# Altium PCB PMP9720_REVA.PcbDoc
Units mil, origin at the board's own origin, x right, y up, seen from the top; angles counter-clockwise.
Board outline 4500 x 2000 mil, 4 copper layers (Top Layer, MidLayer1, MidLayer2, Bottom Layer), stack 60.2 mil thick; 90 components, 43 nets, 263 pads, 74 vias.
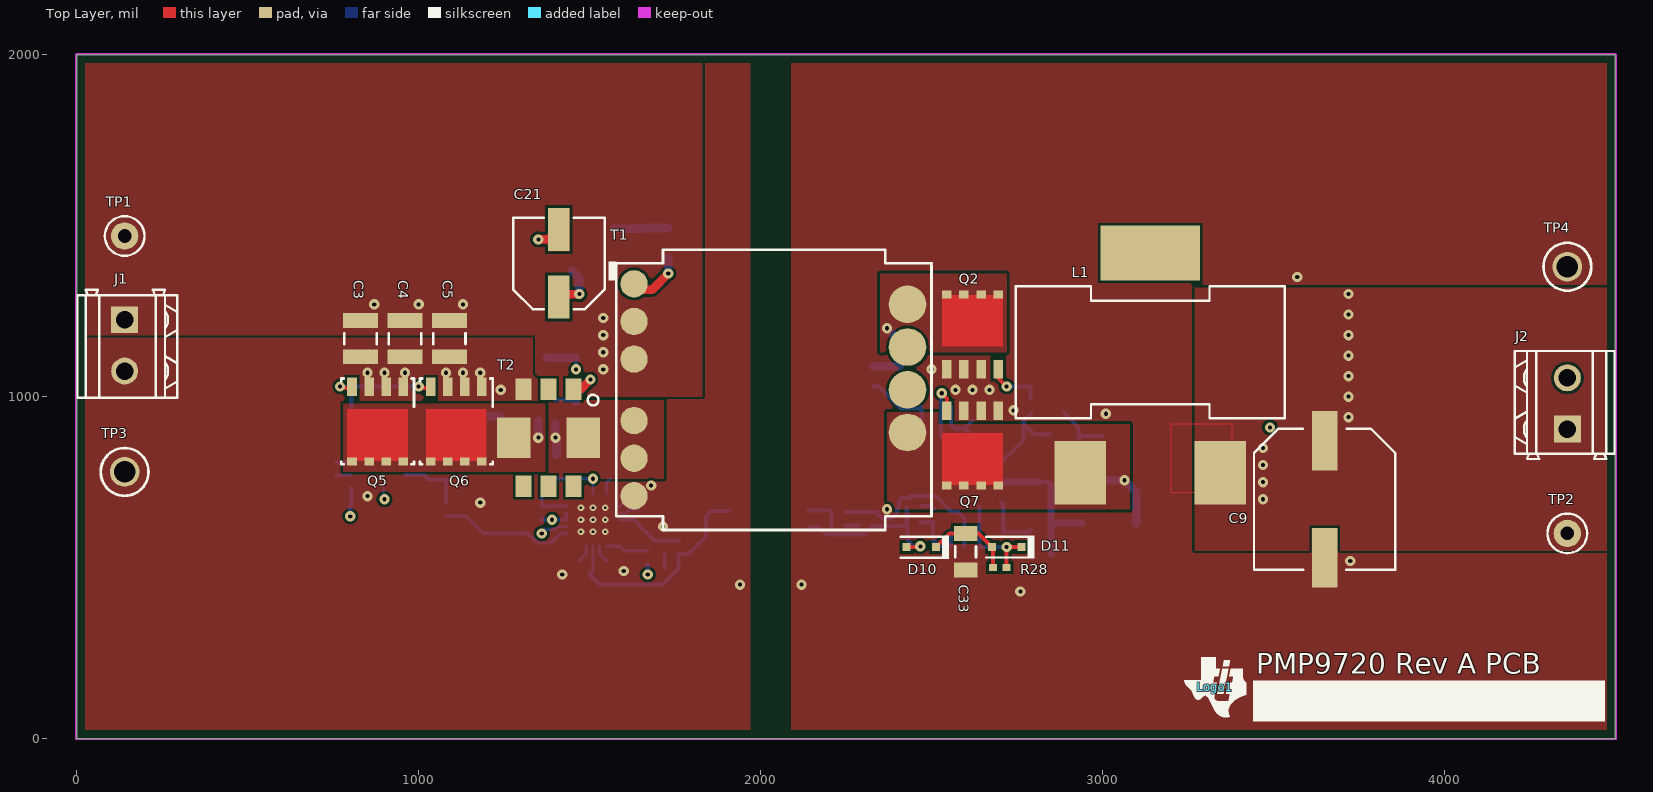
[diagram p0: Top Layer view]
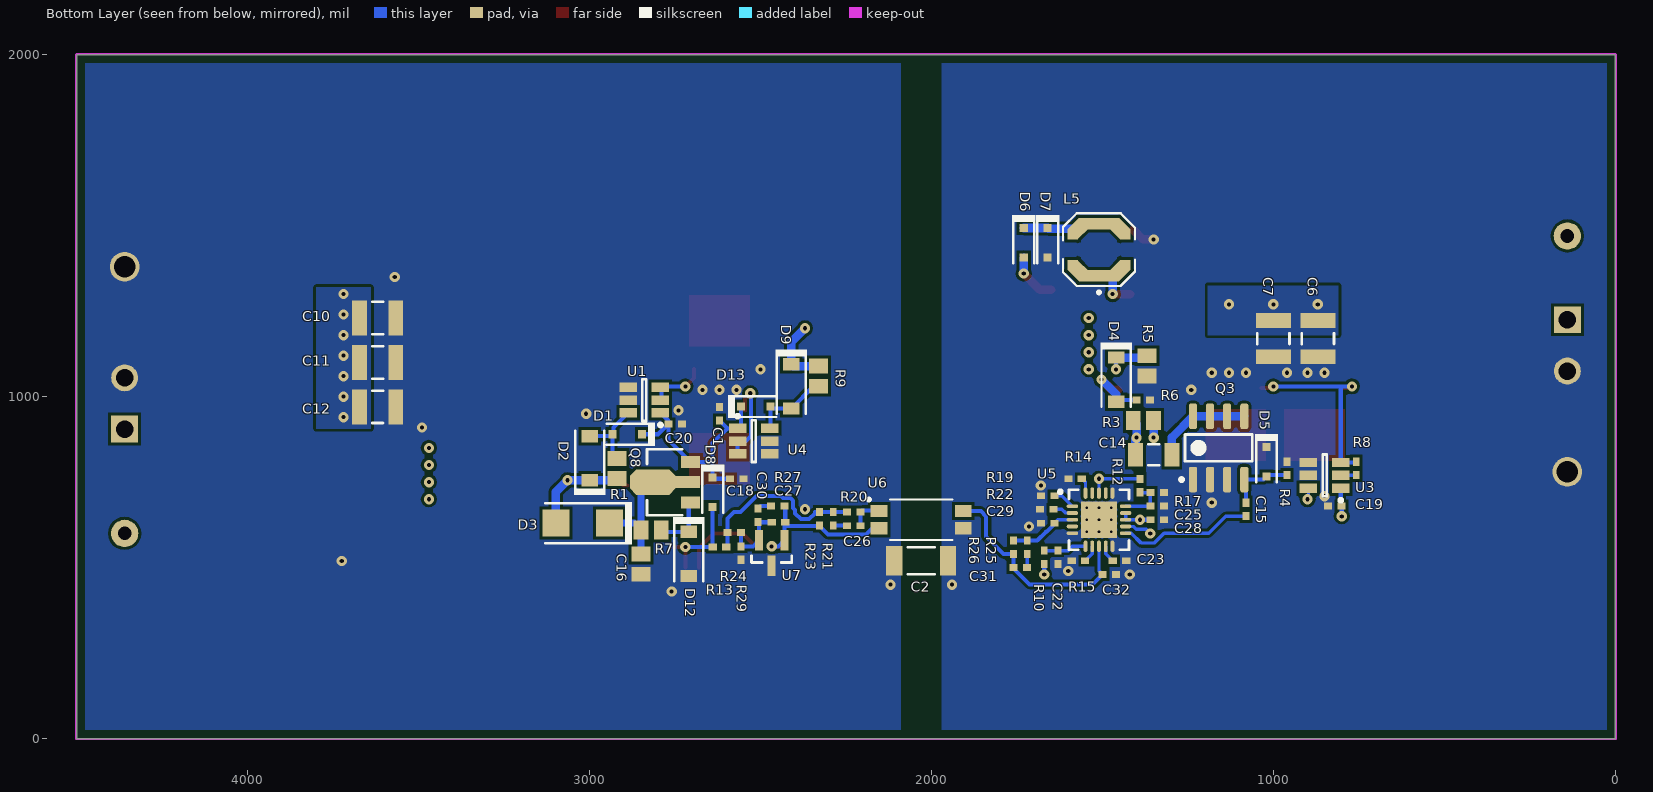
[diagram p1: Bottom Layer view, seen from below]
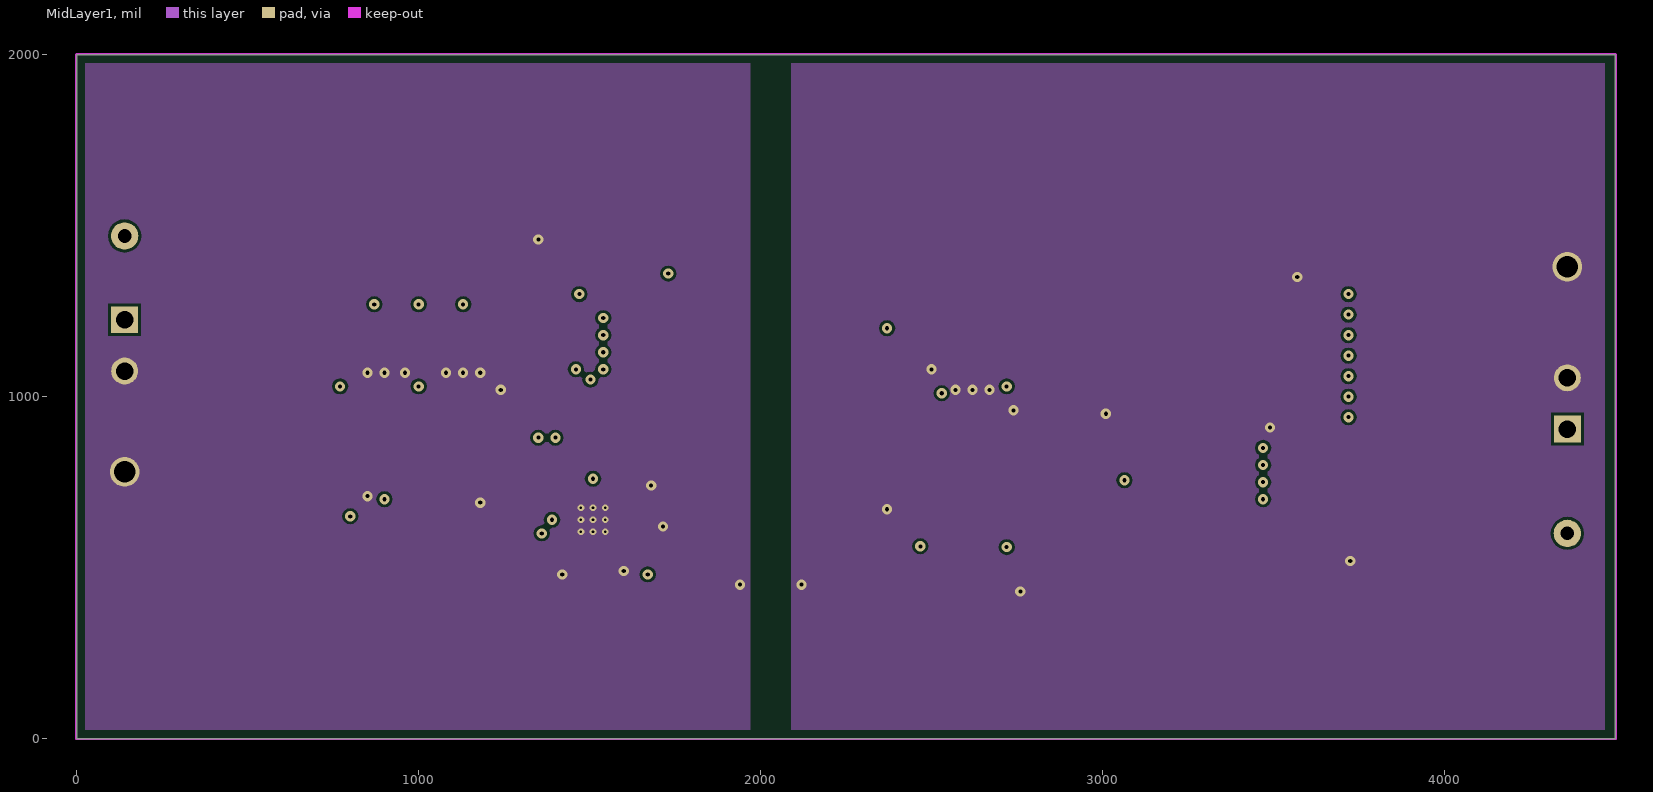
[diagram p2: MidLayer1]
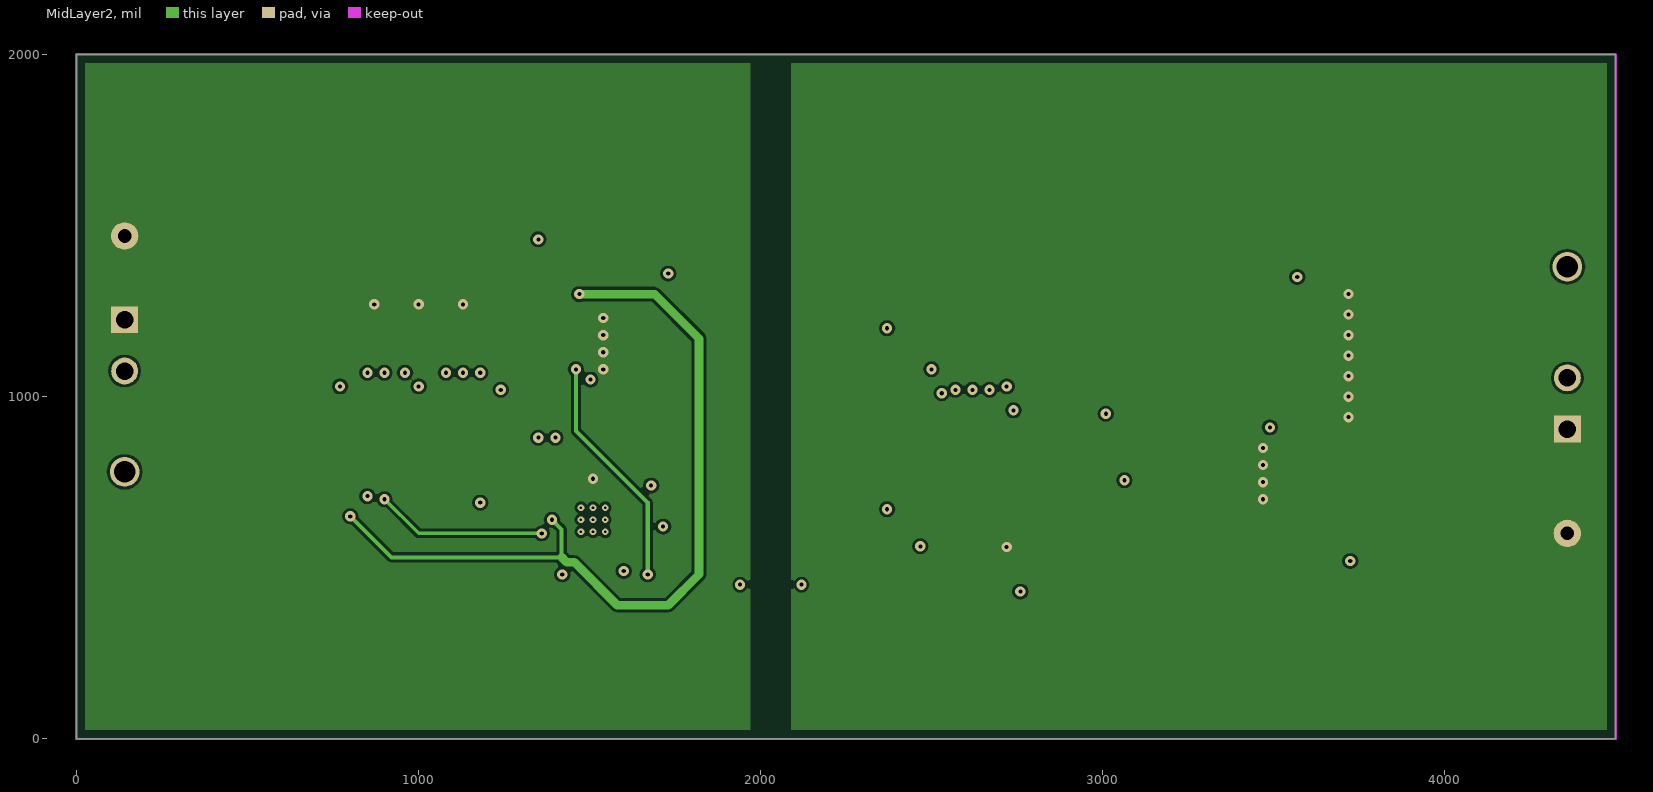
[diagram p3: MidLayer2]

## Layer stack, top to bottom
Top Layer: signal copper 1.4
Dielectric: core 18.2, FR-4, Dk 4.8
MidLayer1: signal copper 1.4
Dielectric: prepreg 18.2, FR-4, Dk 4.8
MidLayer2: signal copper 1.4
Dielectric: core 18.2, FR-4, Dk 4.8
Bottom Layer: signal copper 1.4

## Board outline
0,0 4500,0 4500,2000 0,2000

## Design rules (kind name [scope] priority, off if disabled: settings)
AcuteAngle [All] p1: minimum=7.00000000000000E+0000 checktracksonly=TRUE
AssemblyTestPointUsage [All] p1: valid=2
Clearance Clearance_BoardEdge_MountingHoles [OnCopper and InComponentClass('Mounting Holes') vs IsKeepOut] p1: gap=25
Clearance Clearance_BoardEdge_Poly [OnCopper and InPoly vs IsKeepOut] p2: gap=25
Clearance Clearance_BoardEdge [OnCopper and Not InComponentClass('Logo') and not InComponentClass('FiducialMark') and not InRegion(1000,500,4000,800) and Not IsKeepout vs IsKeepOut] p3: gap=25
Clearance Clearance_Poly [InPolygon] p4: gap=8
Clearance [All] p5: gap=8
ComponentClearance ComponentClearance_Shunt [InComponentClass('Header') vs InComponentClass('Shunt')] p1: gap=0 collisioncheckmode=3 verticalgap=0 showdistances=FALSE
ComponentClearance ComponentClearance_Logo [InComponentClass('Logo')] p2: gap=15 collisioncheckmode=3 verticalgap=10 showdistances=FALSE
ComponentClearance ComponentClearance_ScrewToNut [(HasFootprint('NY PMS 440 0025 PH')) vs (HasFootprint('Keystone_1902C'))] p3: gap=5 collisioncheckmode=3 verticalgap=10 showdistances=FALSE
ComponentClearance ComponentClearance_MountingHoles [InComponentClass('Mounting Holes')] p4: gap=15 collisioncheckmode=3 verticalgap=100000 showdistances=FALSE
ComponentClearance ComponentClearance_SmallPassives [HasFootprint('0201*') or HasFootprint('0402*') or HasFootprint('0508') or HasFootprint('0603*') or HasFootprint('0612') or HasFootprint('0805*') or HasFootprint('0815*') or HasFootprint('0830*') or HasFootprint('1206*') or HasFootprint('1210*') or HasFootprint('1808*') or HasFootprint('1812*') or HasFootprint('1825*') or HasFootprint('2010*') or HasFootprint('2220*') or HasFootprint('2225*') or HasFootprint('2512*') or HasFootprint('2728*') or HasFootprint('3518*') vs HasFootprint('0201*') or HasFootprint('0402*') or HasFootprint('0508') or HasFootprint('0603*') or HasFootprint('0612') or HasFootprint('0805*') or HasFootprint('0815*') or HasFootprint('0830*') or HasFootprint('1206*') or HasFootprint('1210*') or HasFootprint('1808*') or HasFootprint('1812*') or HasFootprint('1825*') or HasFootprint('2010*') or HasFootprint('2220*') or HasFootprint('2225*') or HasFootprint('2512*') or HasFootprint('2728*') or HasFootprint('3518*')] p5: gap=15 collisioncheckmode=3 verticalgap=10 showdistances=FALSE
ComponentClearance ComponentClearance_THtoSMT [IsThruComponent vs IsSMTComponent] p6: gap=15 collisioncheckmode=3 verticalgap=30 showdistances=FALSE
ComponentClearance ComponentClearance_THtoTH [IsThruComponent vs IsThruComponent] p7: gap=15 collisioncheckmode=3 verticalgap=30 showdistances=FALSE
ComponentClearance [All] p8: gap=15 collisioncheckmode=3 verticalgap=10 showdistances=FALSE
DiffPairsRouting [All] p1: maxlimit=100 minlimit=10 mostfreqgap=10 maxuncoupledlength=1000
FabricationTestPointUsage TestPointUsage [All] p1: valid=2 allowmultiple=FALSE
FabricationTestpoint Testpoint [All] p1: side=3 testpointundercomponent=TRUE minsize=40 maxsize=100 preferedsize=60 minholesize=0 maxholesize=40 preferedholesize=32 testpointgrid=1 allowsidetop=TRUE allowsidebottom=TRUE usegrid=TRUE gridtolerance=0.01
FanoutControl Fanout_LCC [IsLCC] p1: bgadir=Out bgaviamode=Centered fanoutstyle=Auto fanoutdirection=Alternating viagrid=1 // Fanout_LCC (Default Rule)
FanoutControl Fanout_BGA [IsBGA] p2: bgadir=Out bgaviamode=Centered fanoutstyle=Auto fanoutdirection=Alternating viagrid=1 // Fanout_BGA (Default Rule)
FanoutControl Fanout_Default [All] p4: bgadir=Out bgaviamode=Centered fanoutstyle=Auto fanoutdirection=Alternating viagrid=1 // Fanout_Default (Default Rule)
FanoutControl Fanout_Small [(CompPinCount < 5)] p5: bgadir=Out bgaviamode=Centered fanoutstyle=Auto fanoutdirection=OutThenIn viagrid=1 // Fanout_Small (Default Rule)
HoleSize [All] p1: absolutevalues=TRUE maxlimit=251 minlimit=8 maxpercent=80.000 minpercent=20.000
MinimumAnnularRing MinimumAnnularRing_ThermalPadVias [IsVia and InAnyComponent] p1: minimumring=5.91
MinimumAnnularRing [All] p2: minimumring=9
MinimumSolderMaskSliver MinimumSolderMaskSliver_Logo [InComponentClass('Logo') vs InComponentClass('Logo')] p1: minsoldermaskwidth=0.7
MinimumSolderMaskSliver [All] p2: minsoldermaskwidth=0
PlaneConnect [All] p1: planeconnectstyle=Relief reliefexpansion=10 reliefentries=4 reliefconductorwidth=10 reliefairgap=10
PolygonConnect [All] p1: connectstyle=Direct reliefconductorwidth=10 reliefentries=4 polygonreliefangle="90 Angle" airgapwidth=10
RoutingVias ThermalPadVias [IsVia and InAnyComponent] p1: holewidth=7.87 width=19.68 viastyle="Through Hole" minholewidth=7.87 minwidth=19.68 maxholewidth=12.99 maxwidth=23.62
RoutingVias [All] p2: holewidth=16 width=34 viastyle="Through Hole" minholewidth=7.87 minwidth=26 maxholewidth=40 maxwidth=65
SMDToCorner [All] p1: distance=0
SilkToSilkClearance [All] p1: silktosilkclearance=0
SilkscreenOverComponentPads [All] p1: minsilkscreentomaskgap=0
SolderMaskExpansion [All] p1: expansion=1.97
Width [All] p1: maxlimit=100 minlimit=6 preferedwidth=10 checkconnectedcopper=TRUE
14 further rules are at their usual default settings.

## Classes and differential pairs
component class Logo: Logo1

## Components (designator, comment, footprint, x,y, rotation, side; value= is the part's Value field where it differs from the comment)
C1 "C1005X7R1H104M" 0402L 2620,950 r90 bottom
C2 "STD" 1808_L 2030,520 r180 bottom
C3 "GRM32ER72A225KA35L" 1210L 830,1170 r270 top
C4 "GRM32ER72A225KA35L" 1210L 960,1170 r270 top
C5 "GRM32ER72A225KA35L" 1210L 1090,1170 r270 top
C6 "GRM32ER72A225KA35L" 1210L 870,1170 r270 bottom
C7 "GRM32ER72A225KA35L" 1210L 1000,1170 r270 bottom
C9 "16SVP330M" SM_RADIAL_10AMM 3650,700 r270 top
C10 "GRM32ER61E226KE15L" 1210L 3620,1230 r180 bottom
C11 "GRM32ER61E226KE15L" 1210L 3620,1100 r180 bottom
C12 "GRM32ER61E226KE15L" 1210L 3620,970 r180 bottom
C14 "C3216X7R2E104K" 1206L 1350,830 r0 bottom
C15 "C1005X7R1H104M" 0402L 1080,670 r90 bottom
C16 "C2012X7R2A473K" 0805L 2850,510 r270 bottom
C18 "C1005X7R1H104M" 0402L 2570,760 r180 bottom
C19 "C1005X7R1H104M" 0402L 820,680 r180 bottom
C20 "C1005X7R1H104M" 0402L 2750,920 r180 bottom
C21 "EEE-FK1C221XP" SM_RADIAL_D8 1410,1390 r90 top
C22 "CC0402KRX7R9BB101" 0402L 1630,530 r90 bottom
C23 "GRM155R61A224KE19D" 0402L 1450,520 r0 bottom
C25 "GRM155R71E473KA88D" 0402L 1340,680 r0 bottom
C26 "N/A" 0402L 2227.4,622.6 r180 bottom
C27 "C1005X7R1E103K" 0402L 2447.4,632.6 r0 bottom
C28 "C1005X7R1H104M" 0402L 1340,640 r180 bottom
C29 "GRM155R61A105KE15D" 0402L 1660,630 r0 bottom
C30 "N/A" 0402L 2507.4,652.6 r90 bottom
C31 "N/A" 0402L 1740,500 r180 bottom
C32 "C1005X7R1H102K" 0402L 1480,480 r180 bottom
C33 "C3216X7R1E475K" 1206L 2600,546.22 r270 top
D1 "BAS316,115" sod-323 2890,890 r0 bottom
D2 "BAV21W-7-F" SOD-123 3000,820 r90 bottom
D3 "US1B-13-F" SMA 3020,630 r0 bottom
D4 "BAV21W-7-F" SOD-123 1460,1050 r270 bottom
D5 "BAS316,115" sod-323 1020,810 r270 bottom
D6 "BAS316,115" sod-323 1730,1450 r270 bottom
D7 "BAS316,115" sod-323 1660,1450 r270 bottom
D8 "BAS316,115" sod-323 2640,720 r270 bottom
D9 "BAV21W-7-F" SOD-123 2410,1030 r270 bottom
D10 "BAS316,115" sod-323 2470,559.68 r180 top
D11 "BAS316,115" sod-323 2720,560 r180 top
D12 "MMSZ4692-V" SOD-123 2710,540 r270 bottom
D13 "BAS316,115" sod-323 2514.09,971.02 r180 bottom
J1 "691214310002" Wurth_691214310002 140,1150 r270 top
J2 "691214310002" Wurth_691214310002 4360,980 r90 top
L1 "SER2013-472MLB" SER2013 3140,1130 r90 top
L5 "LPS4414-105MLB" LPS4414 1510,1430 r90 bottom
Logo1 "Texas Instruments" TI_Symbol_Overlay_Small 3330,150 r0 top
Q2 "CSD18532Q5B" TRANS_NexFET_Q5B#1 2620,1190 r90 top
Q3 "IRF6216TRPBF" SO-8L 1160,850 r90 bottom
Q5 "DNP" TRANS_NexFET_Q5B#2 880,920 r270 top
Q6 "FDMS86255" TRANS_NexFET_Q5B#2 1110,920 r270 top
Q7 "CSD18532Q5B" TRANS_NexFET_Q5B#1 2620,850 r270 top
Q8 "BCX5616TA" SOT-89-3 2780,750 r0 bottom
R1 "CRCW08055K10JNEA" 0805L 2920,790 r90 bottom
R3 "ERJ-6RSJR10V" 0805L 1380,930 r0 bottom
R4 "CRCW040210K0FKED" 0402L 960,790 r270 bottom
R5 "CRCW08053R30JNEA" 0805L 1370,1090 r90 bottom
R6 "CRCW040210K0FKED" 0402L 1380,990 r0 bottom
R7 "CRCW080520K0FKEA" 0805L 2820,610 r0 bottom
R8 "CRCW04020000Z0ED" 0402L 757.48,790 r90 bottom
R9 "CRCW08055K10JNEA" 0805L 2330,1060 r270 bottom
R10 "CRCW04021K00FKED" 0402L 1670,530 r90 bottom
R12 "CRCW0402301KFKED" 0402L 1390,740 r90 bottom
R13 "CRCW04020000Z0ED" 0402L 2620,560 r0 bottom
R14 "CRCW040210K0FKED" 0402L 1580,760 r180 bottom
R15 "CRCW0402100KFKED" 0402L 1570,520 r180 bottom
R17 "CRCW04028K66FKED" 0402L 1340,720 r0 bottom
R19 "CRCW040257K6FKED" 0402L 1660,710 r180 bottom
R20 "CRCW04022K00FKED" 0402L 2227.4,662.6 r0 bottom
R21 "N/A" 0402L 2287.4,642.6 r270 bottom
R22 "CRCW040275K0FKED" 0402L 1662.84,671.05 r180 bottom
R23 "CRCW04024K99FKED" 0402L 2327.4,642.6 r90 bottom
R24 "CRCW040210K0FKED" 0402L 2577.4,602.6 r0 bottom
R25 "N/A" 0402L 1720,560 r270 bottom
R26 "CRCW04021K00FKED" 0402L 1760,560 r270 bottom
R27 "N/A" 0402L 2450,680 r0 bottom
R28 "CRCW040210K0FKED" 0402L 2700,500 r0 top
R29 "CRCW04022K61FKED" 0402L 2557.4,542.6 r90 bottom
T1 "RA7040-AL" Coilcraft_RA7040-AL 2040,1020 r0 top
T2 "CST2-100L" XFMR_COILCRAFT_8X8p13MM6P 1380,880 r270 top
TP1 "5000" Keystone5000 140,1470 r0 top
TP2 "5000" Keystone5000 4360,600 r0 top
TP3 "5011" Keystone5011 140,780 r0 top
TP4 "5011" Keystone5011 4360,1380 r0 top
U1 "UCC27511DBV" DBV0006A_M 2840,990 r0 bottom
U3 "UCC27511DBV" DBV0006A_M 850,770 r0 bottom
U4 "UCC27511DBV" DBV0006A_M 2520,870 r180 bottom
U5 "UCC2897ARGPR" RGP0020D 1510,640 r180 bottom
U6 "VOS617A-7X001T" SSOP-4_VISHAY 2030,640 r180 bottom
U7 "TL431AIDBZ" DBZ0003A_N 2467.4,542.6 r270 bottom

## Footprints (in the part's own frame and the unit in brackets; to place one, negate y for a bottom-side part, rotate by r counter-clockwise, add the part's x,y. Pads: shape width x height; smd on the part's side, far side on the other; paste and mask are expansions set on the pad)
0402L [mm] "0402 from SM-752 data"
  rect 0.6x0.5 smd: 1(-0.5,0) 2(0.5,0)
  body extent -0.55,-0.3 0.55,0.3, height 0.6
0805L [mm] "0805 from SM-752 data"
  rect 1.1x1.4 smd: 1(-0.75,0) 2(0.75,0)
  body extent -1.1,-0.72 1.1,0.72, height 1.1
1206L [mm] "1206 from SM-752 data"
  rect 1.1x1.75 smd: 1(-1.35,0) 2(1.35,0)
  silkscreen extent -0.4,-0.77 0.4,0.77, body extent -1.7,-0.9 1.7,0.9, height 1.35
1210L [mm] "1210 from SM-752 data"
  rect 1.1x2.6 smd: 1(-1.35,0) 2(1.35,0)
  silkscreen extent -0.4,-1.2 0.4,1.2, body extent -1.7,-1.35 1.7,1.35, height 1.35
1808_L [mm] "Chip Capacitor, Body 4.6x2.0mm, IPC High Density"
  rect 1.2x2.2 smd: 1(-2,0) 2(2,0)
  silkscreen extent -1,-1 1,1, body extent -2.47,-1.2 2.47,1.2, height 2.03
Coilcraft_RA7040-AL [mil] "COILCRAFT"
  round 80 smd: 1(-410,310) 2(-410,200) 3(-410,90) 4(-410,-90) 5(-410,-200) 6(-410,-310)
  round 110 smd: 8(390,-125) 9(390,0) 10(390,125) 11(390,250)
  silkscreen extent -485,-410 460,410, body extent -460,-410 460,410, height 352
DBV0006A_M [mm] "SOT23, 6-Leads, Body 2.9x1.6mm, Pitch 0.95mm, Lead Span 2.8mm, IPC Low Density"
  rect 1.3x0.7 smd: 1(-1.2,0.95) 2(-1.2,0) 3(-1.2,-0.95) 4(1.2,-0.95) 5(1.2,0) 6(1.2,0.95)
  silkscreen extent -1.32,-1.55 0.15,1.97, body extent -1.42,-1.46 1.42,1.46, height 1.11
DBZ0003A_N [mm] "SOT23, 3-Leads, Body 2.9x1.3mm, Pitch 0.95mm, Lead Span 2.4mm, IPC Medium Density"
  rect 1.5x0.6 smd: 1(-0.95,0.95) 2(-0.95,-0.95) 3(0.95,0)
  silkscreen extent 0.2,-1.5 0.7,1.5, body extent -1.26,-1.46 1.26,1.46, height 0.96
Keystone5000 [mil] "For Keystone 500x miniature loop terminals"
  round 80 hole 40: 1(0,0)
  silkscreen extent -58,-58 58,58, body extent -49,-49 49,49, height 182
Keystone5011 [mil] "Keystone Multipurpose loops"
  round 87 hole 63: 1(0,0)
  silkscreen extent -70,-70 70,70, body extent -63,-63 63,62, height 319
LPS4414 [mm] "Coilcraft recommended land pattern Document 548-2 10/1/10"
  rect 0.85x3 smd: 1(-1.925,0) 2(1.925,0)
  rect 1.202x1.07 smd rot 135: 1(-1.55,-1.55) 2(1.55,1.55)
  rect 1.202x1.07 smd rot 45: 1(-1.55,1.55) 2(1.55,-1.55)
  rect 0.75x0.775 smd: 1(-1.125,-1.963) 1(-1.125,1.963) 2(1.125,-1.963) 2(1.125,1.963)
  silkscreen extent -3.26,-2.68 2.7,2.68, body extent -2.2,-2.2 2.2,2.2, height 1.42
RGP0020D [mm] "QFN, 20-Leads, Body 4x4mm, Pitch 0.5mm, Thermal Pad 2.7x2.7mm, TI Recommended"
  oval 0.85x0.28 smd paste-0.025 mask+0.07: 1(-1.975,1) 2(-1.975,0.5) 3(-1.975,0) 4(-1.975,-0.5) 5(-1.975,-1) 11(1.975,-1) 12(1.975,-0.5) 13(1.975,0) 14(1.975,0.5) 15(1.975,1)
  oval 0.28x0.85 smd paste-0.025 mask+0.07: 6(-1,-1.975) 7(-0.5,-1.975) 8(0,-1.975) 9(0.5,-1.975) 10(1,-1.975) 16(1,1.975) 17(0.5,1.975) 18(0,1.975) 19(-0.5,1.975) 20(-1,1.975)
  rect 2.7x2.7 smd paste-1.35 mask+0.07: 21(0,0)
  silkscreen extent -3,-2.22 2.22,2.22, body extent -2.07,-2.07 2.07,2.07, height 1
SER2013 [mil] "Coilcraft recommended land pattern.  Document 349-1, rev 02/24/10"
  rect 185x150 smd: 1(-352.25,205) 2(-352.25,-205)
  rect 160x290 smd: 3(290.25,0)
  silkscreen extent -193,-394 193,394, body extent -412,-390 324,390, height 510
SM_RADIAL_10AMM [mm] "10 x 7.9mm:  Sanyo Oscon F8"
  rect 4.4x1.9 smd: 1(-4.35,0) 2(4.35,0)
  silkscreen extent -5.25,-5.25 5.25,5.25, body extent -5.26,-5.26 5.26,5.26, height 8
SM_RADIAL_D8 [mm] "6.3 x 7.7mm:  Panasonic D8"
  rect 3.2x1.6 smd: 1(-2.5,0) 2(2.5,0)
  silkscreen extent -3.4,-3.4 3.4,3.4, body extent -3.41,-3.41 3.41,3.41, height 8.01
SMA [mm] "Molded Diode, 2-Leads, Body 4.3x2.6mm, IPC Medium Density, based on OnSemi component dimensions and land pattern"
  rect 2x2 smd: 1(-2,0) 2(2,0)
  silkscreen extent -3.66,-1.57 2.79,1.57, body extent -2.6,-1.3 2.6,1.3, height 2.42
SO-8L [mm] "SOIC, 8-Leads, Body 5.0x4.0mm (max), Pitch 1.27mm, IPC Most Density"
  rrect50% 1.9x0.6 smd: 1(-2.35,1.905) 2(-2.35,0.635) 3(-2.35,-0.635) 4(-2.35,-1.905) 5(2.35,-1.905) 6(2.35,-0.635) 7(2.35,0.635) 8(2.35,1.905)
  silkscreen extent -2.47,-2.5 1,2.88, body extent -3,-2.45 3,2.45, height 1.59
SOD-123 [mm] "On Semi recommended land pattern"
  rect 0.915x1.22 smd: 1(-1.637,0) 2(1.637,0)
  silkscreen extent -2.74,-1.17 2.03,1.17, body extent -1.93,-0.9 1.93,0.9, height 1.35
sod-323 [mm] "NXP recommended land pattern"
  rect 0.6x0.6 smd paste-0.05: 1(-1.1,0) 2(1.1,0)
  silkscreen extent -2.06,-0.86 1.53,0.86, body extent -1.3,-0.67 1.3,0.68, height 1.1
SOT-89-3 [mm] "SOT, 3-Leads, Body 4.6 x 2.6 mm, Pitch 1.5mm"
  rect 1.4x0.9 smd: 1(-1.9,1.5) 3(-1.9,-1.5)
  rect 1.8x0.9 smd: 2(-1.7,0)
  oct 3.4x1.9 smd: 4(0.9,0)
  silkscreen extent -1.3,-2.45 1.33,2.45, body extent -2.42,-2.28 1.83,2.32, height 1.62
SSOP-4_VISHAY [mm] "Vishay Recommened"
  rect 1.25x0.9 smd: 1(-3.125,0.635) 2(-3.125,-0.635) 3(3.125,-0.635) 4(3.125,0.635)
  silkscreen extent -3.98,-1.5 2.3,1.59, body extent -3.5,-1.45 3.5,1.45, height 2.42
TI_Symbol_Overlay_Small [mil]
  silkscreen extent -90,-88 91,88
TRANS_NexFET_Q5B#1 [mm] "TI recommended land pattern (nominal) November 2012"
  rect 1.372x0.71 smd paste-0.4 mask+0.051: 1(-2.776,1.905) 2(-2.776,0.635) 3(-2.776,-0.635) 4(-2.776,-1.905)
  rect 0.59x0.71 smd paste-0.3: 5(2.776,-1.905) 6(2.776,-0.635) 7(2.776,0.635) 8(2.776,1.905)
  Top Layer region: -1.106,-2.26 2.744,-2.26 2.744,2.26 -1.106,2.26
  body extent -3.23,-2.55 2.87,2.55, height 1.06
TRANS_NexFET_Q5B#2 [mm] "TI recommended land pattern (nominal) November 2012"
  rect 1.372x0.71 smd paste-0.4: 1(-2.776,1.905) 2(-2.776,0.635) 3(-2.776,-0.635) 4(-2.776,-1.905)
  rect 0.59x0.71 smd paste-0.3: 5(2.776,-1.905) 6(2.776,-0.635) 7(2.776,0.635) 8(2.776,1.905)
  Top Layer region: -1.106,-2.26 2.744,-2.26 2.744,2.26 -1.106,2.26
  silkscreen extent -3.38,-2.7 3,2.7, body extent -3.23,-2.55 2.87,2.55, height 1.06
Wurth_691214310002 [mm] "WE"
  rect 2x2 hole 1.3: 1(-1.905,0)
  round 2 hole 1.3: 2(1.905,0)
  silkscreen extent -4.12,-3.5 3.9,3.9, body extent -4.12,-3.5 3.9,3.9, height 8.52
XFMR_COILCRAFT_8X8p13MM6P [mil] "XFMR, Coilcratf 8x13x5.3mm"
  rect 63x47 smd: 1(-141.5,73) 2(-141.5,0) 3(-141.5,-73) 4(141.5,-73) 5(141.5,0) 6(141.5,73)
  rect 118x98 smd: 7(0,-102) 8(0,102)
  silkscreen extent -126,114 -94,146, body extent -123,-123 123,123, height 209

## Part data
C1 C15 C18 C19 C20 C28: "CAP, CERM, 0.1uF, 50V, +/-20%, C0G/NP0, 0402"
C2: library part VJ1808Y102KXEAT5Z, "CAP, CERM, 1000pF, 3kV, 1808"
C3 C4 C5 C6 C7: "CAP, CERM, 2.2uF, 100V, +/-10%, X7R, 1210"
C9: "CAP, OS-CON, 330uF, 16V, +/-20%, 0.016 ohm, 10x10.3 SMD"
C10 C11 C12: "CAP, CERM, 22uF, 25V, +/-10%, X5R, 1210"
C14: "CAP, CERM, 0.1uF, 250V, +/-10%, X7R, 1206"
C16: "CAP, CERM, 0.047uF, 100V, +/-10%, X7R, 0805"
C21: "CAP, AL, 220uF, 16V, +/-20%, 0.34 ohm, SMD"
C22: "CAP, CERM, 100pF, 50V, +/-10%, X7R, 0402"
C23: "CAP, CERM, 0.22uF, 10V, +/-10%, X5R, 0402"
C25: "CAP, CERM, 0.047uF, 25V, +/-10%, X7R, 0402"
C26 C30 C31: library part 04025C132KAT2A, "Do Not Populate"
C27: "CAP, CERM, 0.01uF, 25V, +/-10%, X7R, 0402"
C29: "CAP, CERM, 1uF, 10V, +/-10%, X5R, 0402"
C32: "CAP, CERM, 1000pF, 50V, +/-10%, X7R, 0402"
C33: "CAP, CERM, 4.7uF, 25V, +/-10%, X7R, 1206"
D1 D5 D6 D7 D8 D10 D11 D13: "Diode, Ultrafast, 100V, 0.25A, SOD-323"
D2 D4 D9: "Diode, Switching, 200V, 0.2A, SOD-123"
D3: "Diode, Ultrafast, 100V, 1A, SMA"
D12: "Diode, Zener, 6.8V, 500mW, SOD-123"
J1 J2: "Terminal Block, 2x1, 3.81mm, 24-16 AWG, 10A, 300VAC, TH"
L1: "Inductor, Shielded E Core, Ferrite, 4.7uH, 18A, 0.0017 ohm, SMD"
L5: "Inductor, Shielded Drum Core, Ferrite, 1mH, 0.11A, 16.3 ohm, SMD"
Logo1: library part TI_Logo, "Texas Instrument Corporate Signature"
Q2 Q7: "MOSFET, N-CH, 60V, 172A, SON 5x6mm"
Q3: "MOSFET, P-CH, -150V, -2.2A, SO-8"
Q5: library part FDMS86255, "Do Not Populate"
Q6: "MOSFET, N-CH, 150V, 10A, SON 5x6mm"
Q8: library part "BCX5616TA, Diodes Inc.", "Transistor, NPN, 80V, 1A, SOT-89"
R1 R9: "RES, 5.1k ohm, 5%, 0.125W, 0805"
R3: "RES, 0.1 ohm, 5%, 0.125W, 0805"
R4 R6 R14 R24 R28: "RES, 10.0k ohm, 1%, 0.063W, 0402"
R5: "RES, 3.3 ohm, 5%, 0.125W, 0805"
R7: "RES, 20.0k ohm, 1%, 0.125W, 0805"
R8 R13: "RES, 0 ohm, 5%, 0.063W, 0402"
R10 R26: "RES, 1.00k ohm, 1%, 0.063W, 0402"
R12: "RES, 301k ohm, 1%, 0.063W, 0402"
R15: "RES, 100k ohm, 1%, 0.063W, 0402"
R17: "RES, 8.66k ohm, 1%, 0.063W, 0402"
R19: "RES, 57.6k ohm, 1%, 0.063W, 0402"
R20: "RES, 2.00k ohm, 1%, 0.063W, 0402"
R21 R25 R27: library part CRCW0402133RFKED, "Do Not Populate"
R22: "RES, 75.0k ohm, 1%, 0.063W, 0402"
R23: "RES, 4.99k ohm, 1%, 0.063W, 0402"
R29: "RES, 2.61k ohm, 1%, 0.063W, 0402"
T1: "Transformer, 50uH, SMT"
T2: "Transformer, 2000uH, SMT"
TP1 TP2: "Test Point, Miniature, Red, TH"
TP3 TP4: "Test Point, Multipurpose, Black, TH"
U1 U3 U4: "Single-Channel High-Speed Low-Side Gate Driver (with 4-A Peak Source and 8-A Peak Sink), DBV0006A"
U5: "Advanced Active Clamp PWM Controller with Current Control, -40 to +125 degC, 20-pin QFN (RGP), Green (RoHS & no Sb/Br)"
U6: "OptoCoupler, Phototransitor, 80-160%, SSOP-4"
U7: "PRECISION PROGRAMMABLE REFERENCE, DBZ0003A"

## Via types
v1: diameter 30, hole 12, Top Layer to Bottom Layer, 65 vias
v2: diameter 19.68, hole 7.87, Top Layer to Bottom Layer, 9 vias

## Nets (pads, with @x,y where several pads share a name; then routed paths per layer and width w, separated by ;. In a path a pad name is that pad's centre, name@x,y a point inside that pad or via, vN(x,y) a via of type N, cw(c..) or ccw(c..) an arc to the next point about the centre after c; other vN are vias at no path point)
BIAS: C19.2 C21.1 C28.1 L5.1 U3.1 U5.13 U5.14 | length 2685.8
  Top Layer w25: C21.1@1418.43,1300 v1(1470,1300)
  MidLayer2 w12: v1(800,650) 920,530 1418.35,530 1418.35,611.65 v1(1390,640)
  MidLayer2 w25: 1418.35,530 1432.85,515.5 1455.5,515.5 1581,390 1730,390 1820,480 1820,1170 1690,1300 v1(1470,1300)
  Bottom Layer w10: v1(1390,640) U5.13 U5.14
  Bottom Layer w12: v1(800,650) 800,679.69 C19.2 802.76,682.44 U3.1 ; C28.1 v1(1390,640)
  Bottom Layer w25: L5.1@1448.98,1368.98 1470,1347.95 v1(1470,1300)
CS: D4.1 R5.2 R10.1 | length 836.7
  MidLayer2 w12: v1(1460,1080) 1460,900.05 1670,690.05 v1(1670,480)
  Bottom Layer w12: v1(1460,1080) D4.1 ; v1(1670,480) R10.1
  Bottom Layer w25: R5.2@1375.06,1114.47 D4.1
GND: C1.2 C2.1 C9.2 C10.2 C11.2 C12.2 C16.2 C18.2 C20.2 C33.2 D12.2 J2.2 Q2.1 Q2.2 Q2.3 Q7.1 Q7.2 Q7.3 R29.1 TP4.1 U1.4 U1.5 U4.4 U4.5 U7.3
  other v1: 2760,430 2120,450 3724.9,519.18 2370,670.67 3490,910 3010,950 2740,960 2570,1020 2620,1020 2670,1020 2500,1080 3570,1350
N_DRV: U3.6 U5.12 | length 611.9
  MidLayer2 w10: v1(900,700) 1000,600 v1(1360,600)
  Bottom Layer w10: v1@897.24,702.76 U3.6 ; v1(1360,600) 1372,612 1401.6,612 1409.91,620.32 U5.12
NetC14_1: C14.1 Q3.5 Q3.6 Q3.7 Q3.8 | length 288.1
  Bottom Layer w25: Q3.5 Q3.6 Q3.7 Q3.8 1296.85,880.67 C14.1
NetC14_2: C14.2 R3.2 T1.4 T1.5 T2.8 | length 91.8
  Bottom Layer w25: R3.2@1400,920.47 v1(1400,880) 1403.15,876.85 C14.2
NetC15_2: C15.2 D5.2 Q3.4 R4.2 | length 195.1
  Bottom Layer w12: R4.2 D5.2@1016.38,770.31 ; D5.2 1029.21,757.48 Q3.4 1080,752.48 C15.2
NetC16_1: C16.1 D3.1 Q8.2 Q8.4 R7.2 | length 441.8
  Bottom Layer w12: Q8.4 2840,750 Q8.4@2849.53,740.47 ; R7.2 2850,610.47 R7.2@2869.53,630
  Bottom Layer w20: Q8.2 Q8.4 ; R7.2 Q8.4@2849.53,740.47 ; C16.1 R7.2@2850,610.47 ; R7.2@2869.53,630 D3.1
NetC22_2: C22.2 R10.2 U5.6 | length 125.8
  Bottom Layer w10: U5.6 1587.76,562.24 1600.31,549.69 C22.2 R10.2
NetC23_2: C23.2 U5.9 | length 50.8
  Bottom Layer w10: C23.2 1490.32,540.63 U5.9
NetC25_2: C25.2 R12.1 R17.2 U5.15 | length 140.7
  Bottom Layer w10: R12.1@1389.06,719.37 1360.32,719.37 1360.32,679.37 U5.15
NetC26_1: C26.1 R21.2 | length 40
  Bottom Layer w12: C26.1 R21.2@2287.09,622.6
NetC26_2: C26.2 R20.1 U6.1 | length 109.4
  Bottom Layer w12: U6.1@2140.43,667.6 2202.72,667.6 R20.1 C26.2
NetC27_1: C27.1 D10.2 R23.1 R27.1 U6.2 U7.1 | length 500.2
  Top Layer w12: D10.2 v1@2469.99,559.68
  Bottom Layer w12: U6.2@2140.43,617.6 2171.26,617.6 2191.76,597.1 2303.04,597.1 2327.4,621.46 2427.72,621.46 C27.1 R27.1@2427.72,677.4 ; C27.1@2430,630.32 U7.1 2447.72,562.28 v1(2467.4,562.28)
NetC27_2: C27.2 C30.1 R24.1 R29.2 U7.2 | length 193.9
  Bottom Layer w12: C27.2 2507.09,632.6 2504.8,630.32 U7.2 2522.52,562.28 R29.2 2557.4,602.28 R24.1
NetC29_1: C29.1 R25.1 R26.1 U5.3 | length 198.4
  Bottom Layer w10: U5.3 1630.32,640 C29.1
  Bottom Layer w12: C29.1 1640.32,627.92 1662.08,606.16 1664.16,606.16 1690.63,579.68 R25.1 R26.1
NetC30_2: C30.2 R27.2 | length 40.9
  Bottom Layer w12: R27.2 2499.69,680 C30.2
NetC31_1: C31.1 C32.1 R26.2 U5.8 U6.4 | length 653.4
  Bottom Layer w10: C32.1 1510,490.32 U5.8
  Bottom Layer w12: C32.1 1528.68,451 1712.77,451 1759.68,497.92 C31.1 R26.2@1759.68,540 ; R26.2 1789.69,540.31 1840,590.63 1840,650 1855,665 U6.4
NetC31_2: C31.2 R25.2 | length 40
  Bottom Layer w10: C31.2 R25.2@1720.31,540
NetC33_1: C33.1 D10.1 D11.2 R28.1 | length 257.6
  Top Layer w12: D10.1 2552.99,599.37 C33.1 2637.32,599.37 D11.2 2680.32,556.38 R28.1
NetD1_2: D1.2 D2.2 R1.2 U1.6 | length 223
  Bottom Layer w12: U1.6 2930,909.84 D1.2@2930,884.47 ; R1.2 2933.31,832.83 D1.2 ; D1.2@2938.84,884.47 D2.2
NetD4_2: D4.2 R6.2 T2.1 | length 206.2
  Top Layer w25: T2.1@1453,1020 1472.5,1020 v1(1502.5,1050)
  Bottom Layer w12: R6.2 1455.53,990 D4.2
  Bottom Layer w25: D4.2 1460,1007.5 v1(1502.5,1050)
NetD6_1: D6.1 D7.1 L5.2 | length 159.9
  Bottom Layer w25: L5.2@1571.02,1491.02 1657.72,1491.02 D7.1 D6.1
NetD6_2: D6.2 T1.1 | length 146.2
  Top Layer w25: T1.1@1650,1312.99 1682.99,1312.99 v1(1730,1360)
  Bottom Layer w25: v1(1730,1360) D6.2
NetD9_2: D9.2 D13.2 R9.2 U4.6 | length 234.4
  Bottom Layer w12: R9.2 2345.06,1030.47 D9.2 2465.3,965.53 D13.2 2470.79,909.37 U4.6
NetD12_1: D12.1 Q8.1 R7.1 | length 171.2
  Bottom Layer w12: Q8.1 2710,686.14 D12.1 2784.94,604.47 R7.1
NetQ2_4: Q2.4 U1.2 U1.3 | length 168.6
  Top Layer w12: Q2.4 2695,1055 v1(2720,1030)
  Bottom Layer w12: v1(2720,1030) 2790.16,1030 U1.2@2790.16,992.6
NetQ5_4: Q5.4 Q6.4 R8.2 U3.3 | length 557
  Top Layer w12: v1@774.88,1025.12 Q5.4@805,1025.12 ; v1@1004.88,1025.12 Q6.4@1035,1025.12
  Bottom Layer w12: R8.2@759.76,807.4 U3.3 802.76,1027.24 800,1030 ; v1(770,1030) 800,1030 ; v1(1000,1030) 800,1030
NetQ5_5: Q5.5 Q5.6 Q5.7 Q5.8 Q6.5 Q6.6 Q6.7 Q6.8 R3.1 T2.7 | length 49.5
  Bottom Layer w25: v1(1350,880) R3.1@1350,929.53
NetQ7_4: Q7.4 U4.2 U4.3 | length 265.8
  Top Layer w12: v1(2530,1010) 2545,995 Q7.4
  Bottom Layer w12: v1(2530,1010) 2527.65,1007.65 2527.65,885.48 2543.13,870 U4.2 U4.3
NetR8_1: R8.1 U3.2 | length 45
  Bottom Layer w10: R8.1@757.8,770 U3.2
NetR13_1: R13.1 R20.2 R21.1 R23.2 R24.2 | length 514.8
  Bottom Layer w12: R20.2 R23.2@2327.09,662.6 ; R23.2 2341,662.28 2341,658.66 2357.99,641.67 2382.01,641.67 2399,658.66 2399,669 2404.5,674.5 2404.5,695.64 2412.71,703.84 2433.84,703.84 2440,710 2511.14,710 2558.85,662.28 2578.03,662.28 2597.09,643.23 R24.2 R13.1@2597.09,563.23
NetR14_2: R14.2 U5.20 | length 46.8
  Bottom Layer w10: U5.20 1549.37,749.06 R14.2
NetR15_2: R15.2 U5.7 | length 50.8
  Bottom Layer w10: U5.7 1529.68,540.63 R15.2
NetR19_2: R19.2 U5.1 | length 65.2
  Bottom Layer w10: U5.1 1618.39,710 R19.2
NetR22_2: R22.2 U5.2 | length 60.1
  Bottom Layer w10: U5.2 1607.63,659.68 1619,671.05 R22.2
P_DRV: C15.1 U5.11 | length 396.5
  Bottom Layer w10: C15.1 1139.68,650.32 1189.37,600.63 1319.77,600.63 1348.4,572 1387.05,572 1415.68,600.63 U5.11
PGND: C2.2 C3.2 C4.2 C5.2 C6.2 C7.2 C19.1 C21.2 C22.1 C23.1 C25.1 C28.2 C29.2 C32.2 D5.1 D7.2 J1.2 Q3.1 Q3.2 Q3.3 Q5.1 Q5.2 Q5.3 Q6.1 Q6.2 Q6.3 R4.1 R5.1 R6.1 R14.1 R15.1 R17.1 R19.1 R22.1 T1.6 T2.3 TP3.1 U3.4 U3.5 U5.5 U5.10 U5.16 U5.21 U6.3 | length 71.8
  Top Layer w25: v1(1350,1460) 1381.57,1460 C21.2
  other v1: 1940,450 1420,480 1600,490 1715,620 1180,690 850,708.98 1680,740 1240,1020 850,1070 900,1070 960,1070 1080,1070 1130,1070 1180,1070
  other v2: 1474.57,604.57 1510,604.57 1545.43,604.57 1474.57,640 1510,640 1545.43,640 1474.57,675.43 1510,675.43 1545.43,675.43
VDRV: C1.1 C18.1 C20.1 D1.1 D8.1 D13.1 Q8.3 U1.1 U4.1 | length 673.1
  Bottom Layer w12: D13.1 2557.4,917.24 U4.1 2597.09,907.4 ; C18.1 2636.69,760 D8.1 2640,864.49 2597.09,907.4 ; C1.1 2597.09,907.4 ; 2644.84,809.06 Q8.3 2769.68,873.54 C20.1 ; U1.1 2769.68,929.53 C20.1 ; D1.1 2799.68,890 C20.1
VIN: C3.1 C4.1 C5.1 C6.1 C7.1 J1.1 R12.2 T1.2 T1.3 TP1.1 U5.18 | length 162.2
  Bottom Layer w10: R12.2@1390,760 v1(1510,760) U5.18
  other v1: 1540,1080 1540,1130 1540,1180 1540,1230 870,1270 1000,1270 1130,1270
VOUT: C9.1 C10.1 C11.1 C12.1 D8.2 D11.1 J2.1 L1.2 R13.2 R28.2 TP2.1 | length 300.1
  Top Layer w12: R28.2 v1@2719.69,559.69 ; v1(2720,560) D11.1
  Bottom Layer w12: D8.2 2640,560.31 R13.2 v1(2720,560)
  other v1: 3470,700 3470,750 3470,800 3470,850 3720,940 3720,1000 3720,1060 3720,1120 3720,1180 3720,1240 3720,1300
VSEC1: D9.1 Q2.5 Q2.6 Q2.7 Q2.8 R9.1 T1.11 | length 204.1
  Bottom Layer w25: R9.1 2405.06,1089.53 D9.1 2410,1160 v1(2370,1200)
VSEC2: D2.1 D3.2 L1.1 Q7.5 Q7.6 Q7.7 Q7.8 R1.1 T1.8 | length 296.2
  Top Layer w12: L1.1@2890,740 L1.1@2900,740
  Bottom Layer w25: R1.1 2924.94,755.53 D2.1 v1(3064.47,755.53) 3098.74,721.26 D3.2
pads on no net: L1.3 T1.9 T1.10 T2.2 T2.4 T2.5 T2.6 U5.4 U5.17 U5.19

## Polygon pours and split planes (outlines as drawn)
VSEC2 on Top Layer "Top Layer-VSEC2" (solid, remove dead copper, pour order 20): 3200,920 3200,720 3380,720 3380,920
VSEC2 on Top Layer "Top Layer-VSEC2" (solid, remove dead copper, pour order 21): 2370,955 2370,765 2520,765 2520,955
VSEC2 on Top Layer "Top Layer-VSEC2" (solid, remove dead copper, pour order 22): 2370,920 2370,670 3080,670 3080,920
VSEC1 on Top Layer "Top Layer-VSEC1" (solid, remove dead copper, pour order 24): 2350,1360 2350,1130 2720,1130 2720,1360
PGND on Top Layer "Top Layer-PGND" (solid, remove dead copper, pour order 29): 10,1980 10,10 1970,10 1970,1980
VIN on Top Layer "Top Layer-VIN" (solid, remove dead copper, pour order 27): 1341.46,1200 1341.46,1000 1830,1000 1830,1200
VIN on Top Layer "Top Layer-VIN" (solid, remove dead copper, pour order 26): 10,1990 10,1180 1830,1180 1830,1990
NetQ5_5 on Top Layer "Top Layer-Drain2" (solid, remove dead copper, pour order 25): 778.74,980 778.74,780 1370,780 1370,980
NetC14_2 on Top Layer "Top Layer-Drain1" (solid, remove dead copper, pour order 19): 1380,990 1380,760 1717.32,760 1717.32,990
VOUT on Top Layer "Top Layer-VOUT" (solid, remove dead copper, pour order 23): 3270,1318.97 3270,550 4497.79,550 4497.79,1318.97
GND on Top Layer "Top Layer-GND" (solid, remove dead copper, pour order 28): 2090,1990 2090,-2.5 4480,-2.5 4480,1990
PGND on Bottom Layer "Bottom Layer-PGND" (solid, remove dead copper, pour order 35): 20,1990 20,10 1970,10 1970,1990
VIN on Bottom Layer "Bottom Layer-VIN" (solid, remove dead copper, pour order 34): 810,1324.99 810,1180 1191.26,1180 1191.26,1324.99
GND on Bottom Layer "Bottom Layer-GND" (solid, remove dead copper, pour order 36): 2090,2000 2090,20 4497.79,20 4497.79,2000
VOUT on Bottom Layer "Bottom Layer-VOUT" (solid, remove dead copper, pour order 33): 3640,1320 3640,906.69 3800,906.69 3800,1320
VIN on MidLayer2 "MidLayer2-VIN" (solid, remove dead copper, pour order 32): 10,1990 10,10 1970,10 1970,1990
VOUT on MidLayer2 "MidLayer2-VOUT" (solid, remove dead copper, pour order 31): 2090,1990 2090,10 4497.79,10 4497.79,1990
GND on MidLayer1 "MidLayer1-GND" (solid, remove dead copper, pour order 30): 2090,1990 2090,0 4470,0 4470,1990
PGND on MidLayer1 "MidLayer1-PGND" (solid, remove dead copper, pour order 30): 10,1990 10,0 1970,0 1970,1990

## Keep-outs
Keep-Out Layer:
  lines w5: -2.5,0 ccw(c0,0) 0,-2.5 ; -2.5,0 ccw(c0,0) 0,-2.5 ; -2.5,0 -2.5,2000 ; -2.5,2000 cw(c0,2000) 0,2002.5 ; -2.5,2000 cw(c0,2000) 0,2002.5 ; 0,-2.5 4500,-2.5 ; 0,2002.5 4500,2002.5 ; 4500,-2.5 ccw(c4500,0) 4502.5,0 ; 4500,-2.5 ccw(c4500,0) 4502.5,0 ; 4500,2002.5 cw(c4500,2000) 4502.5,2000 ; 4500,2002.5 cw(c4500,2000) 4502.5,2000 ; 4502.5,0 4502.5,2000
  text ".Layer_Name" at 577,-858.49 h60

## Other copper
Top Layer:
  text ".Layer_Name" at 577,-858.49 h60
Bottom Layer:
  text ".Layer_Name" at 577,-858.49 h60

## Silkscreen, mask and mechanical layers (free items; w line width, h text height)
Top Overlay:
  rectangle: 3440,50 4470,170
  text "PMP9720 Rev A PCB" at 3450,190 h60
  text ".Layer_Name" at 577,-858.49 h60
Bottom Overlay:
  text ".Layer_Name" at 577,-858.49 h60
Top Paste:
  text ".Layer_Name" at 577,-858.49 h60
Bottom Paste:
  text ".Layer_Name" at 577,-858.49 h60
Top Solder:
  text ".Layer_Name" at 577,-858.49 h60
  text ".Layer_Name" at 577,-858.49 h60
Bottom Solder:
  text ".Layer_Name" at 577,-858.49 h60
Drill Guide:
  text ".Layer_Name" at 577,-858.49 h60
M1 Board Outline:
  the board outline again, w10
  text ".Layer_Name" at 577,-858.49 h60
M2 Board Dimensions:
  rectangle: 124.5,-410.5 499.5,-285.5
  rectangle: -0.5,-285.5 124.5,-160.5
  lines w7: -0.5,-285.5 999.5,-285.5 ; 124.5,-410.5 124.5,-160.5 ; 249.5,-410.5 249.5,-160.5 ; 499.5,-410.5 499.5,-160.5 ; 749.5,-410.5 749.5,-160.5 ; -0.5,-410.5 -0.5,-160.5 999.5,-160.5 999.5,-410.5 -0.5,-410.5
  lines w10: -0.5,-475.5 -0.5,-455.5 ; 59.5,-485.5 -0.5,-465.5 ; 59.5,-445.5 -0.5,-465.5 ; 223.58,-465.5 -0.5,-465.5 ; 775.42,-465.5 999.5,-465.5 ; 939.5,-485.5 999.5,-465.5 ; 939.5,-445.5 999.5,-465.5 ; 999.5,-475.5 999.5,-455.5
  text "1000 (mil)" at 233.58,-501.49 h60
  text ".Layer_Name" at 577,-858.49 h60
M3 3D STEP Top:
  text ".Layer_Name" at 577,-858.49 h60
M4 3D STEP Bottom:
  text ".Layer_Name" at 577,-858.49 h60
M5 Assembly Top:
  lines w10: -292,-930.17 6308,-930.17 ; -292,-726.83 6310,-726.83 ; -292,-523.5 -292,-1133.5 3713,-1133.5 6310,-1133.5 6310,-523.5 -291.5,-523.5 -291.5,-1133.5 1284,-1133.5 ; 2173,-1133.5 2173,-523.5 ; 3440,-726.83 3440,-523.5 ; 4280,-726.83 4280,-523.5 ; 4902,-1140 4902,-937.17
  text "COMPONENTS MARKED 'DNP' SHOULD NOT BE POPULATED." at 1153.5,-318.5 h60
  text "ASSEMBLY VARIANT:" at 1153,-434 h60
  text ".VariantName" at 2189,-434 h60
  text "PCB VIEWED FROM TOP SIDE" at -228.5,-655.67 h60
  text "BOARD #:" at 2248,-655.67 h60
  text ".PRJ_Number" at 2793.5,-655.67 h60
  text "REV:" at 3638,-655.67 h60
  text ".PCB_Rev" at 3929.5,-655.67 h60
  text "SVN REV:" at 4476,-655.67 h60
  text ".VersionControl_RevNumber" at 4982,-655.67 h60
  text "IGNORE ->" at -228.5,-858.49 h60
  text "PLOT NAME =" at -228.5,-1064.34 h60
  text ".plot_File_Name" at 577,-1064.34 h60
  text "GENERATED    :" at 2250,-1064.34 h60
  text ".Print_Date" at 3119.5,-1064.34 h60
  text ".Print_Time" at 3848.5,-1064.34 h60
  text "TEXAS INSTRUMENTS" at 5113,-1064.34 h60
M6 Assembly Bottom:
  lines w10: -292.5,-727.33 6309.5,-727.33 ; -290.5,-930.67 6309.5,-930.67 ; 1115.5,-1140.5 1115.5,-937.67 ; 1737.5,-727.33 1737.5,-524 ; 2577.5,-727.33 2577.5,-524 ; 3844.5,-1134 3844.5,-524 ; 4733.5,-1134 6309,-1134 6309,-524 -292.5,-524 -292.5,-1134 2304.5,-1134 6309.5,-1134 6309.5,-524
  text "COMPONENTS MARKED 'DNP' SHOULD NOT BE POPULATED." at 6102,-318 h60
  text ".VariantName" at 5058,-434 h60
  text "ASSEMBLY VARIANT:" at 6097,-434 h60
  text ".VersionControl_RevNumber" at 1035.5,-656.17 h60
  text "SVN REV:" at 1541.5,-656.17 h60
  text ".PCB_Rev" at 2088,-656.17 h60
  text "REV:" at 2379.5,-656.17 h60
  text ".PRJ_Number" at 3224,-656.17 h60
  text "BOARD #:" at 3769.5,-656.17 h60
  text "PCB VIEWED FROM BOTTOM SIDE" at 6246,-656.17 h60
  text "IGNORE ->" at 2547.85,-858.49 h60
  text "TEXAS INSTRUMENTS" at 904.5,-1064.84 h60
  text ".Print_Time" at 2169,-1064.84 h60
  text ".Print_Date" at 2898,-1064.84 h60
  text "GENERATED    :" at 3767.5,-1064.84 h60
  text ".plot_File_Name" at 5440.5,-1064.84 h60
  text "PLOT NAME =" at 6246,-1064.84 h60
M9 Title Sheet:
  drawing of 57 lines, arcs and shapes, not listed
  text "1" at 739.84,8036.5 h70
  text "2" at 3235.5,8036.5 h70
  text "3" at 5724.84,8036.5 h70
  text "4" at 8231.51,8036.5 h70
  text "5" at 10730.5,8036.5 h70
  text "6" at 13235.5,8036.5 h70
  text "A" at -416.5,6893.5 h70
  text "A" at 14383.5,6893.5 h70
  text "B" at -416.5,4513.5 h70
  text "B" at 14383.5,4513.5 h70
  text "C" at -416.5,2138.5 h70
  text "C" at 14383.5,2138.5 h70
  text "PROJECT TITLE:" at 11343.5,277.5 h45
  text ".PRJ_Title" at 11393.5,144.17 h70
  text "DESIGNED FOR:" at 11343.5,-23.5 h45
  text ".PRJ_Customer" at 11393.5,-163.5 h70
  text "D" at -416.5,-231.5 h70
  text "D" at 14383.5,-231.5 h70
  text "FILE NAME:" at 11343.5,-323.5 h45
  text ".PCB_File_Name_No_Path" at 11393.5,-443.5 h70
  text "Texas Instruments (TI) and/or its licensors do not warrant the accuracy or completeness of this specification" at 6374,-605.34 h45
  text "ENGINEER:" at 11343.5,-613.5 h45
  text "LAYOUT BY:" at 12848.5,-613.5 h45
  text "or any information contained therein. TI and/or its licensors do not warrant that this design will meet" at 6329.01,-718 h45
  text ".PRJ_Engineer" at 11393.5,-768.49 h70
  text ".PCB_Layout" at 12899,-768.49 h70
  text "the specifications, will be suitable for your application or fit for any particular purpose, or will operate in" at 6329.01,-830.67 h45
  text ".Layer_Name" at 577,-858.49 h60
  text "ALTIUM DESIGNER VERSION:" at 12848.5,-923.5 h45
  text "an implementation. TI and/or its licensors do not warrant that the design is production worthy. You should" at 6329.01,-943.33 h45
  text "completely validate and test your design implementation to confirm the system functionality for your application." at 6374,-1056 h45
  text ".print_Scale" at 11393.5,-1056.83 h70
  text ".Application_BuildNumber" at 12899,-1056.83 h70
  text "1" at 739.84,-1263.5 h70
  text "2" at 3235.5,-1263.5 h70
  text "3" at 5724.84,-1263.5 h70
  text "4" at 8231.51,-1263.5 h70
  text "5" at 10730.5,-1263.5 h70
  text "6" at 13235.5,-1263.5 h70
M10 Fab Notes:
  drawing of 212 lines, arcs and shapes, not listed
  text "DESIGN INFORMATION" at 12381.02,6810 h60
  text "(REFER ALSO ARRAY/PANEL PROFILING INFORMATION)" at 12019.46,6648.29 h60
  text "BOARD SIZE" at 11333.46,6644 h60
  text "X" at 12301.46,6516.18 h60
  text "Number of Layers :" at 11736.46,6319 h60
  text "4" at 12831.27,6309 h60
  text "MIN. TRACK WIDTH:" at 11736.46,6180 h60
  text "8" at 12832.7,6180 h60
  text "MIL" at 12987.46,6180 h60
  text "MIN. CLEARANCE:" at 11736.46,6048 h60
  text "8" at 12832.7,6048 h60
  text "MIL" at 12987.46,6048 h60
  text "MIN. VIA PAD SIZE:" at 11736.46,5916 h60
  text "24" at 12802.71,5916 h60
  text "MIL" at 12987.46,5916 h60
  text "0.05mm (2MIL)" at 12431.46,5774.29 h60
  text "MINIMUM ANNULAR RING" at 11407.23,5770 h60
  text "EXTERNAL" at 13139.46,5770 h60
  text "PER" at 11607.23,5652 h60
  text "IPC-D-275 CLASS 2 LEVEL C" at 11827.23,5652 h60
  text "MIL, HOLES" at 13315.46,5539.71 h60
  text "+/-" at 12923,5539 h60
  text "+/-" at 13777,5539 h60
  text "REGISTRATION TOLERANCES:" at 11407.23,5534 h60
  text "METAL" at 12607,5534 h60
  text "5" at 13183.2,5534 h60
  text "3" at 14016.2,5534 h60
  text "MIL" at 14132.46,5534 h60
  text "MATERIAL:" at 11332.46,5324.54 h60
  text "FR-4 High Tg" at 12318.9,5184.21 h60
  text "FR-408" at 11753.46,5175.64 h60
  text "X" at 12165.46,5175.64 h60
  text "OTHER" at 13241.46,5175.64 h60
  text "62 MIL (1.6mm) +/-10%" at 12073.56,5012.92 h60
  text "THICKNESS:" at 11407.23,5008.64 h60
  text "X" at 11945.4,5008.64 h60
  text "OTHER" at 13358.46,5008.64 h60
  text "TOLERANCE:" at 11407.23,4850.64 h60
  text "X" at 12246.53,4850.64 h60
  text "ANSI IPC-6012 TYPE 3 CLASS 2" at 12433.48,4850.64 h60
  text "OTHER +/-" at 12433.46,4694.64 h60
  text "BOW & TWIST:" at 11407.23,4537.64 h60
  text "X" at 12246.53,4537.64 h60
  text "ANSI IPC-6012 TYPE 3 CLASS 2" at 12433.48,4537.64 h60
  text "OTHER +/-" at 12433.46,4379.13 h60
  text "COPPER THICKNESS (FINISHED):" at 11332.46,4243.64 h60
  text "1.4MIL (1oz)" at 12212.46,4090.92 h60
  text "2MIL (1.4oz)" at 12979.46,4090.92 h60
  text "2.8MIL (2oz)" at 13706.46,4090.92 h60
  text "OUTER:" at 11689.46,4086.64 h60
  text "X" at 12084,4086 h60
  text "1.4MIL (1oz)" at 12212.46,3933.92 h60
  text "2.8MIL (2oz)" at 12979.46,3933.92 h60
  text "N/A" at 13706,3934.29 h60
  text "INNER SIGNAL:" at 11400.38,3929.64 h60
  text "X" at 12085.42,3929.64 h60
  text "DRILLING:" at 11332.46,3790.64 h60
  text "REFERENCE:" at 11407.23,3673.64 h60
  text "X" at 12055.46,3673.64 h60
  text "AS SHOWN" at 12242.46,3673.64 h60
  text "X" at 12956.46,3673.64 h60
  text "NC_DRILL FILES" at 13093.46,3673.64 h60
  text "PTH MIN COPPER THICKNESS:" at 11407.23,3515.64 h60
  text "X" at 12757.46,3515.64 h60
  text "1MIL" at 12894.46,3515.64 h60
  text "OTHER" at 13391.46,3515.64 h60
  text "BOARD FINISH:" at 11332.46,3356.64 h60
  text "SILKSCREEN:" at 11487.68,3238.64 h60
  text "X" at 12436.46,3238.64 h60
  text "TOP" at 12562.46,3238.64 h60
  text "X" at 12946.46,3238.64 h60
  text "BOTTOM" at 13073.46,3238.64 h60
  text "SILKSCREEN COLOR:" at 11487.68,3071.64 h60
  text "X" at 12435.42,3071.64 h60
  text "WHITE" at 12562.46,3071.64 h60
  text "OTHER" at 13073.46,3071.64 h60
  text "SOLDER RESIST COLOR:" at 11487.68,2901.64 h60
  text "X" at 12055.42,2742.44 h60
  text "GREEN" at 12182.46,2742.44 h60
  text "BLUE" at 12773.46,2742.44 h60
  text "OTHER" at 13311.46,2742.44 h60
  text "IMMERSION GOLD (ENIG)" at 12393.46,2553.92 h60
  text "ENEPIG" at 13731,2550.64 h60
  text "SURFACE FINISH:" at 11332.46,2549.64 h60
  text "IMM. TIN/SILVER OR EQUIV" at 11662,2392.64 h60
  text "OTHER" at 13093.46,2392.64 h60
  text "X" at 11490,2390 h60
  text "ARRAY/PANEL:" at 11332.46,2213.64 h60
  text "CUT AND TRIM PER MECH LAYER 1" at 12393.46,2209.35 h60
  text "N.C. ROUTE" at 12393.46,2057.64 h60
  text "X" at 13072.46,2057.64 h60
  text "V. SCORE" at 13259.46,2057.64 h60
  text "CERTIFICATION:" at 11332.46,1920.64 h60
  text "MATERIALS AND WORKMANSHIP FOR ALL PCBS" at 12057.46,1920.64 h60
  text "TO MEET OR EXCEED THE REQUIREMENTS OF:" at 12057.46,1822.64 h60
  text "X" at 11683.96,1686.13 h60
  text "ANSI IPC-A-600F CLASS ->" at 11822.96,1686.13 h60
  text "X" at 13462.02,1686.13 h60
  text "2" at 13580.96,1686.14 h60
  text "1" at 13265.96,1684.64 h60
  text "3" at 13934.96,1684.64 h60
  text "X" at 11686.02,1526.64 h60
  text "UL 94V-0" at 11822.96,1526.64 h60
  text "X" at 12498.02,1526.64 h60
  text "RoHS" at 12634.96,1526.64 h60
  text "OTHER" at 13279.36,1526.64 h60
  text "PER ORDER" at 13676.42,1526.64 h60
  text "ADDITIONAL REQUIREMENTS:" at 11332.46,1385.64 h60
  text "MICROSECTION:" at 11407.23,1270.64 h60
  text "YES" at 12312.96,1270.64 h60
  text "REQUIRED" at 13174.46,1114.49 h60
  text "BARE BOARD ELEC. TEST:" at 11407.23,1111.64 h60
  text "NONE" at 12712.96,1111.64 h60
  text "X" at 13047.46,1111.64 h60
  text "PER ORDER" at 13766.46,1111.64 h60
  text "MANUFACTURER'S UL:" at 11407.23,954.64 h60
  text "RAIL" at 12572.96,950.35 h60
  text "METAL" at 13064.77,950.35 h60
  text "X" at 13440,950 h60
  text "SILK" at 13576.46,950.35 h60
  text ".Layer_Name" at 577,-858.49 h60
M11 Gerber Information:
  lines w10: -292,-930.17 6308,-930.17 ; -292,-726.83 6310,-726.83 ; -292,-523.5 -292,-1133.5 3713,-1133.5 6310,-1133.5 6310,-523.5 -291.5,-523.5 -291.5,-1133.5 1284,-1133.5 ; 2173,-1133.5 2173,-523.5 ; 3440,-726.83 3440,-523.5 ; 4280,-726.83 4280,-523.5 ; 4902,-1140 4902,-937.17
  text "ALL ARTWORK VIEWED FROM TOP SIDE" at -228.5,-655.67 h60
  text "BOARD #:" at 2248,-655.67 h60
  text ".PRJ_Number" at 2793.5,-655.67 h60
  text "REV:" at 3638,-655.67 h60
  text ".PCB_Rev" at 3929.5,-655.67 h60
  text "SVN REV:" at 4476,-655.67 h60
  text ".VersionControl_RevNumber" at 4982,-655.67 h60
  text "LAYER NAME =" at -228.5,-858.49 h60
  text "PLOT NAME =" at -228.5,-1064.34 h60
  text ".plot_File_Name" at 577,-1064.34 h60
  text "GENERATED    :" at 2250,-1064.34 h60
  text ".Print_Date" at 3119.5,-1064.34 h60
  text ".Print_Time" at 3848.5,-1064.34 h60
  text "TEXAS INSTRUMENTS" at 5113,-1064.34 h60
M12 Stackup:
  lines w6: 11350,7698 14230,7698 ; 11350,7814.7 14230,7814.7 ; 11290,6968 ccw(c11328,6968) 11328,6930 14252,6930 ccw(c14252,6968) 14290,6968 14290,7912 ccw(c14252,7912) 14252,7950 11328,7950 ccw(c11328,7912) 11290,7912 11290,6968
  text "Layer Stack Up Detail for: PMP9656_REVA.PcbDoc" at 11350,7843.75 h52
  text "Layer" at 11350,7771.2 h27
  text "Gerber" at 12359.79,7771.2 h27
  text "Copper" at 13002.9,7771.2 h27
  text "Dielectric" at 13690.1,7771.2 h27
  text "Name" at 11350,7717.2 h27
  text "Document" at 12359.79,7717.2 h27
  text "Thickness" at 13002.9,7717.2 h27
  text "Material" at 13690.1,7717.2 h27
  text "Top Solder Mask" at 11350,7641.88 h38
  text "(.GTS)" at 12359.79,7641.88 h38
  text "Solder Resist" at 13690.1,7641.88 h38
  text "Top Layer" at 11350,7535.62 h38
  text "(.GTL)" at 12359.79,7535.62 h38
  text "1.4mil" at 13002.9,7535.62 h38
  text "FR-4" at 13690.1,7482.5 h38
  text "MidLayer1" at 11350,7429.38 h38
  text "(.G1)" at 12359.79,7429.38 h38
  text "1.4mil" at 13002.9,7429.38 h38
  text "FR-4" at 13690.1,7376.25 h38
  text "MidLayer2" at 11350,7323.12 h38
  text "(.G2)" at 12359.79,7323.12 h38
  text "1.4mil" at 13002.9,7323.12 h38
  text "FR-4" at 13690.1,7270 h38
  text "Bottom Layer" at 11350,7216.88 h38
  text "(.GBL)" at 12359.79,7216.88 h38
  text "1.4mil" at 13002.9,7216.88 h38
  text "Bottom Solder Mask" at 11350,7110.62 h38
  text "(.GBS)" at 12359.79,7110.62 h38
  text "Solder Resist" at 13690.1,7110.62 h38
  text ".Layer_Name" at 577,-858.49 h60
M13 Component Bodies Top:
  text ".Layer_Name" at 577,-858.49 h60
M14 Component Bodies Bottom:
  text ".Layer_Name" at 577,-858.49 h60
M15 Courtyards Top:
  text ".Layer_Name" at 577,-858.49 h60
M16 Courtyards Bottom:
  text ".Layer_Name" at 577,-858.49 h60
Drill Drawing:
  text ".legend" at 5272.5,195.5 h60
  text "Drill Table" at 5297.5,10.5 h60
  text ".Layer_Name" at 577,-858.49 h60

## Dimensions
0,0 to 4500,0 on M2 Board Dimensions
0,0 to 0,2000 on M2 Board Dimensions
